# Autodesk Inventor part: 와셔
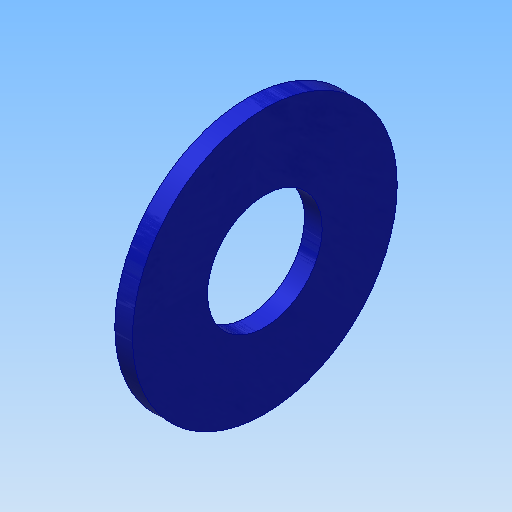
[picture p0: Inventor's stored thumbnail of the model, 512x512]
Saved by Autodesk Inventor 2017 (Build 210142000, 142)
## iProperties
Created: 2015-12
Part Number: 와셔
Material: 스테인리스강
Document SubType Name: Modeling
Designer: mduedu
Density: 8.08 g/cm^3
Appearance: 파란색 - 벽 페인트 - 광택
Author: mduedu
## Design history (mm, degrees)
sketch "스케치1"
  geometry: C1 r 3.25 at (0, 0); C2 r 7.5 at (0, 0); 1 further point
  constraints: 2 centre point, 2 coincident
  dimensions: "d0" = 6.5 diameter of C1; "d1" = 15 diameter of C2
extrude "돌출1" new body sketch "스케치1" stored distance "d2" = 1; taper "d3" = 0 deg
node "솔리드1"
